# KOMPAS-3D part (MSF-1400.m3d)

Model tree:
1. Ось X
2. Ось Y
3. Ось Z
4. Начало координат  (labels: Операция без истории:1)

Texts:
  Линия-выноска #1
  Линия-выноска #2
  Линия-выноска #3
  Отклонения формы и база
  Марка координационной оси
  Марка/позиционное обозначение с линией-выноской
  Марка/позиционное обозначение на линии
  Марка/позиционное обозначение без линии-выноски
